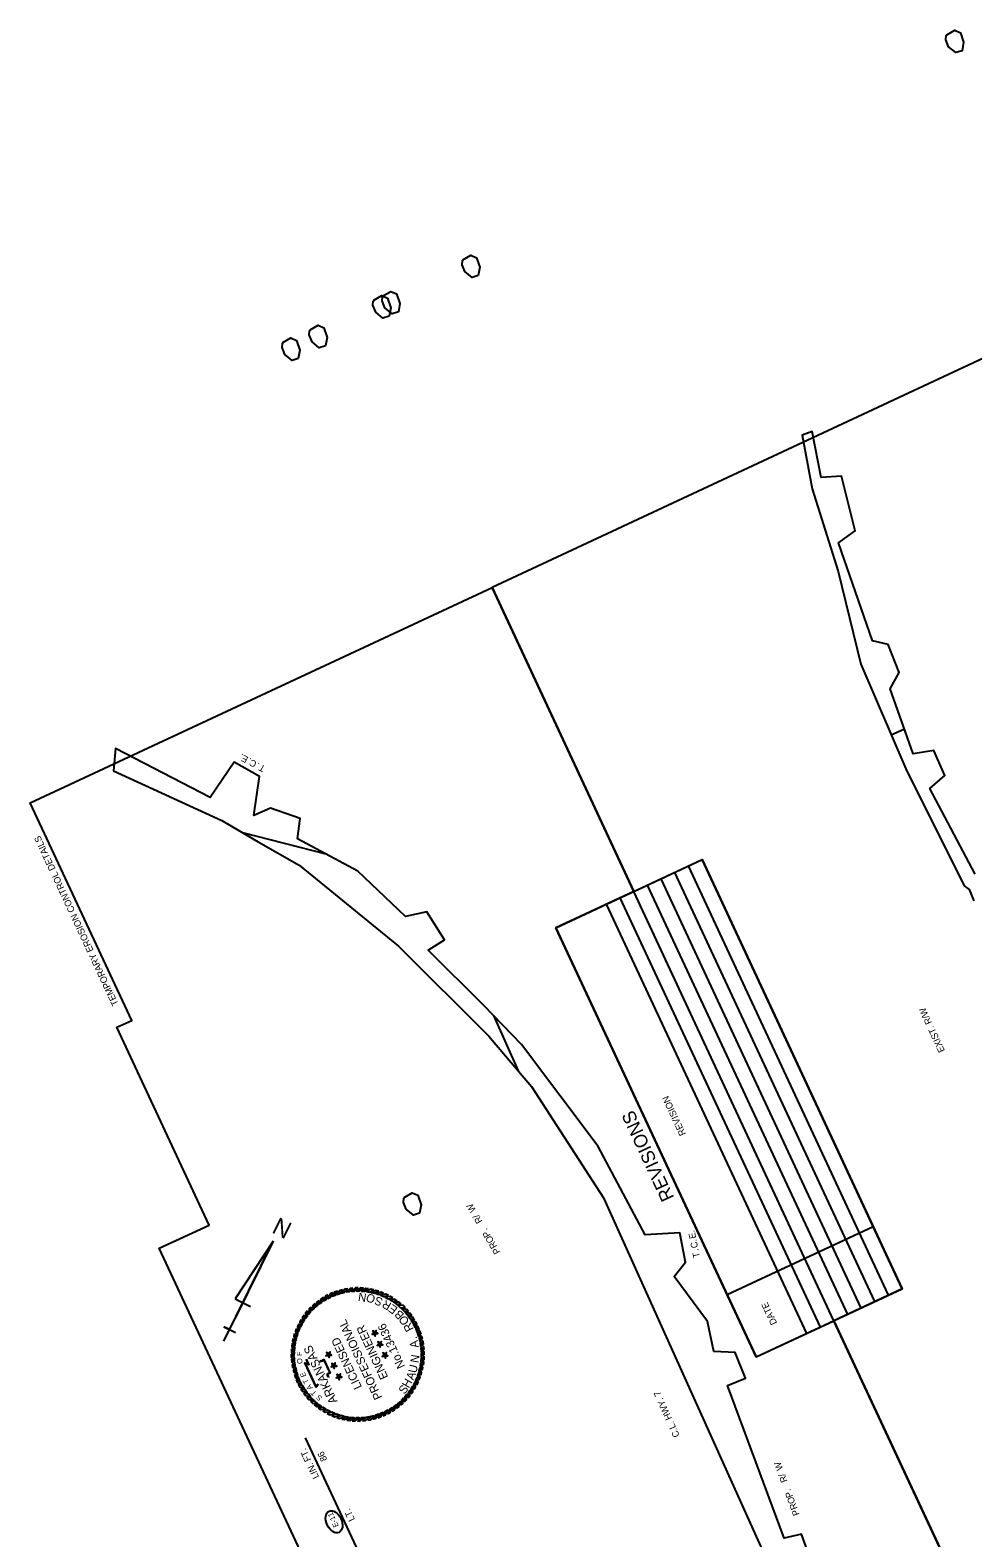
# Model space of a CAD drawing. Extents: x 964229 to 965790, y 1899262 to 1901428.
# Drawn here: x 964229 to 965075, y 1900076 to 1901428 of the extents above; entities that cross this region are included whole.
import ezdxf

# ---------------------------------------------------------------- set-up
doc = ezdxf.new("R2010")
doc.units = 0
for name, color, linetype in [('1', 7, 'Continuous'), ('44', 7, 'Continuous'), ('63', 7, 'Continuous'), ('Default', 7, 'Continuous'), ('G-ANNO-SYMB', 7, 'Continuous'), ('NO PLOT', 7, 'Continuous'), ('R_Draft', 7, 'Continuous'), ('R_Horz Alg Annot', 7, 'Continuous'), ('S_TREE', 7, 'Continuous')]:
    doc.layers.add(name, color=color, linetype=linetype)

msp = doc.modelspace()

# ---------------------------------------------------------------- linework, layer by layer
at = {"layer": '1'}
for p, q in [((964770.4, 1900655.6), (964643.2, 1900928.4)), ((965071, 1900011), (964950, 1900270.4))]:
    msp.add_line(p, q, dxfattribs=at)
msp.add_ellipse((964501.5, 1900090), major_axis=(-4.45, 9.53), ratio=0.638788, dxfattribs=at)
at = {"layer": '44'}
msp.add_line((964574.3, 1899954.5), (964475.9, 1900165.4), dxfattribs=at)
at = {"layer": '63'}
for p, q in [((964402.7, 1900252.1), (964447, 1900341.7)), ((964447, 1900341.7), (964412.8, 1900290)), ((964447, 1900341.7), (964412.9, 1900272.8)), ((964412.8, 1900290), (964426.6, 1900283.1)), ((964402.7, 1900252.1), (964412.9, 1900272.8)), ((964407.8, 1900262.4), (964402.6, 1900265)), ((964402.6, 1900265), (964413, 1900259.9)), ((964402.7, 1900252.1), (964407.8, 1900262.4))]:
    msp.add_line(p, q, dxfattribs=at)
at = {"layer": 'Default'}
for p, q in [((964700.6, 1900623), (964831.6, 1900684.1)), ((964999, 1900293.2), (964819.4, 1900678.4)), ((965011.2, 1900298.9), (964831.6, 1900684.1)), ((964974.5, 1900281.8), (964794.9, 1900667)), ((964986.7, 1900287.5), (964807.1, 1900672.7)), ((964937.8, 1900264.7), (964758.2, 1900649.9)), ((964950, 1900270.4), (964770.4, 1900655.6)), ((964962.3, 1900276.1), (964782.7, 1900661.3)), ((964962.3, 1900276.1), (964782.7, 1900661.3)), ((964925.6, 1900259), (964745.9, 1900644.2)), ((964880.2, 1900237.9), (964700.6, 1900623)), ((964854.1, 1900293.9), (964985.1, 1900354.9)), ((964880.2, 1900237.9), (965011.2, 1900298.9))]:
    msp.add_line(p, q, dxfattribs=at)
at = {"layer": 'G-ANNO-SYMB'}
for points in [[(964504.7, 1900297), (964502.3, 1900296.2), (964499.9, 1900292.3), (964502.4, 1900293.3)], [(964509.2, 1900298.2), (964506.7, 1900297.6), (964504, 1900293.9), (964506.7, 1900294.8)], [(964513.8, 1900299.1), (964511.3, 1900298.7), (964508.3, 1900295.2), (964511, 1900295.9)], [(964518.5, 1900299.7), (964515.9, 1900299.4), (964512.7, 1900296.2), (964515.4, 1900296.6)], [(964523.1, 1900299.8), (964520.6, 1900299.8), (964517.1, 1900296.8), (964519.9, 1900297)], [(964527.8, 1900299.6), (964525.3, 1900299.8), (964521.6, 1900297.1), (964524.3, 1900297.1)], [(964532.5, 1900299), (964529.9, 1900299.4), (964526, 1900297), (964528.8, 1900296.8)], [(964537.1, 1900298.1), (964534.6, 1900298.6), (964530.5, 1900296.6), (964533.2, 1900296.1)], [(964541.6, 1900296.8), (964539.1, 1900297.5), (964534.9, 1900295.8), (964537.6, 1900295.1)], [(964484.3, 1900285.8), (964482.4, 1900284.1), (964481.7, 1900279.5), (964483.6, 1900281.5)], [(964488, 1900288.6), (964486, 1900287.1), (964484.9, 1900282.7), (964487, 1900284.4)], [(964491.9, 1900291.2), (964489.7, 1900289.8), (964488.3, 1900285.5), (964490.6, 1900287.1)], [(964496, 1900293.5), (964493.7, 1900292.3), (964492, 1900288.1), (964494.4, 1900289.5)], [(964500.3, 1900295.4), (964497.9, 1900294.4), (964495.9, 1900290.3), (964498.3, 1900291.6)], [(964545.9, 1900295.1), (964543.6, 1900296.1), (964539.2, 1900294.7), (964541.8, 1900293.8)], [(964550.2, 1900293.1), (964547.9, 1900294.3), (964543.4, 1900293.2), (964546, 1900292.1)], [(964554.3, 1900290.8), (964552.1, 1900292.1), (964547.5, 1900291.4), (964550, 1900290.1)], [(964558.1, 1900288.2), (964556, 1900289.7), (964551.5, 1900289.3), (964553.8, 1900287.9)], [(964561.8, 1900285.3), (964559.8, 1900286.9), (964555.2, 1900286.9), (964557.5, 1900285.3)], [(964565.2, 1900282.1), (964563.4, 1900283.9), (964558.8, 1900284.2), (964560.9, 1900282.4)], [(964472.1, 1900271.6), (964470.8, 1900269.4), (964471.5, 1900264.9), (964472.8, 1900267.4)], [(964474.7, 1900275.5), (964473.2, 1900273.4), (964473.6, 1900268.9), (964475.1, 1900271.2)], [(964477.6, 1900279.2), (964476, 1900277.2), (964476, 1900272.6), (964477.6, 1900274.9)], [(964480.8, 1900282.6), (964479.1, 1900280.8), (964478.7, 1900276.2), (964480.5, 1900278.3)], [(964568.4, 1900278.6), (964566.7, 1900280.5), (964562.2, 1900281.2), (964564.1, 1900279.3)], [(964571.3, 1900274.9), (964569.7, 1900277), (964565.3, 1900278), (964567.1, 1900275.9)], [(964573.8, 1900271), (964572.5, 1900273.2), (964568.1, 1900274.6), (964569.7, 1900272.3)], [(964576.1, 1900266.9), (964574.9, 1900269.2), (964570.7, 1900270.9), (964572.1, 1900268.5)], [(964466.1, 1900258.9), (964465.4, 1900256.5), (964467.1, 1900252.3), (964467.8, 1900255)], [(964467.8, 1900263.3), (964466.8, 1900260.9), (964468.3, 1900256.6), (964469.1, 1900259.2)], [(964469.8, 1900267.6), (964468.7, 1900265.3), (964469.7, 1900260.8), (964470.8, 1900263.4)], [(964538, 1900259.3), (964537, 1900259.5), (964535.6, 1900258.2), (964537.5, 1900258.4)], [(964538, 1900259.3), (964537.9, 1900260.3), (964536.2, 1900261.3), (964537, 1900259.5)], [(964538, 1900259.3), (964537.5, 1900258.4), (964538.4, 1900256.6), (964538.7, 1900258.5)], [(964538, 1900259.3), (964539, 1900259.7), (964539.3, 1900261.7), (964537.9, 1900260.3)], [(964538, 1900259.3), (964538.7, 1900258.5), (964540.7, 1900258.8), (964539, 1900259.7)], [(964578, 1900262.6), (964577, 1900265), (964572.9, 1900267.1), (964574.2, 1900264.6)], [(964579.6, 1900258.2), (964578.8, 1900260.7), (964574.9, 1900263), (964575.9, 1900260.5)], [(964580.9, 1900253.7), (964580.2, 1900256.2), (964576.5, 1900258.9), (964577.4, 1900256.2)], [(964463.3, 1900245.2), (964463.2, 1900242.6), (964465.8, 1900238.9), (964465.9, 1900241.7)], [(964463.9, 1900249.9), (964463.5, 1900247.3), (964465.9, 1900243.4), (964466.2, 1900246.2)], [(964464.8, 1900254.4), (964464.3, 1900251.9), (964466.4, 1900247.9), (964466.8, 1900250.6)], [(964496.6, 1900240), (964497.6, 1900240.4), (964497.9, 1900242.4), (964496.5, 1900241)], [(964542.6, 1900249.4), (964541.6, 1900249.6), (964540.2, 1900248.3), (964542.1, 1900248.5)], [(964542.6, 1900249.4), (964542.5, 1900250.5), (964540.8, 1900251.4), (964541.6, 1900249.6)], [(964542.6, 1900249.4), (964542.1, 1900248.5), (964543, 1900246.7), (964543.3, 1900248.7)], [(964542.6, 1900249.4), (964543.6, 1900249.9), (964544, 1900251.8), (964542.5, 1900250.5)], [(964542.6, 1900249.4), (964543.3, 1900248.7), (964545.3, 1900248.9), (964543.6, 1900249.9)], [(964581.7, 1900249.1), (964581.3, 1900251.6), (964577.8, 1900254.6), (964578.5, 1900251.9)], [(964582.3, 1900244.5), (964582, 1900247), (964578.8, 1900250.2), (964579.2, 1900247.5)], [(964582.4, 1900239.8), (964582.4, 1900242.3), (964579.4, 1900245.8), (964579.6, 1900243.1)], [(964463.1, 1900240.5), (964463.1, 1900238), (964466.1, 1900234.5), (964465.9, 1900237.2)], [(964463.3, 1900235.8), (964463.5, 1900233.3), (964466.7, 1900230.1), (964466.3, 1900232.8)], [(964463.8, 1900231.2), (964464.2, 1900228.7), (964467.7, 1900225.7), (964467.1, 1900228.4)], [(964496.6, 1900240), (964495.6, 1900240.2), (964494.2, 1900238.8), (964496.1, 1900239.1)], [(964496.6, 1900240), (964496.5, 1900241), (964494.8, 1900242), (964495.6, 1900240.2)], [(964496.6, 1900240), (964496.1, 1900239.1), (964497, 1900237.3), (964497.3, 1900239.2)], [(964496.6, 1900240), (964497.3, 1900239.2), (964499.3, 1900239.5), (964497.6, 1900240.4)], [(964501.2, 1900230.1), (964500.2, 1900230.3), (964498.8, 1900229), (964500.7, 1900229.2)], [(964501.2, 1900230.1), (964501.1, 1900231.1), (964499.4, 1900232.1), (964500.2, 1900230.3)], [(964501.2, 1900230.1), (964500.7, 1900229.2), (964501.6, 1900227.4), (964501.9, 1900229.3)], [(964501.2, 1900230.1), (964502.2, 1900230.6), (964502.6, 1900232.5), (964501.1, 1900231.1)], [(964501.2, 1900230.1), (964501.9, 1900229.3), (964503.9, 1900229.6), (964502.2, 1900230.6)], [(964547.2, 1900239.5), (964546.2, 1900239.7), (964544.8, 1900238.4), (964546.7, 1900238.6)], [(964547.2, 1900239.5), (964547.1, 1900240.6), (964545.4, 1900241.5), (964546.2, 1900239.7)], [(964547.2, 1900239.5), (964546.7, 1900238.6), (964547.6, 1900236.8), (964548, 1900238.8)], [(964547.2, 1900239.5), (964548.2, 1900240), (964548.6, 1900241.9), (964547.1, 1900240.6)], [(964547.2, 1900239.5), (964548, 1900238.8), (964549.9, 1900239), (964548.2, 1900240)], [(964580.7, 1900225.9), (964581.2, 1900228.4), (964579.2, 1900232.4), (964578.7, 1900229.7)], [(964581.6, 1900230.4), (964582, 1900233), (964579.6, 1900236.9), (964579.4, 1900234.1)], [(964582.2, 1900235.1), (964582.4, 1900237.7), (964579.7, 1900241.4), (964579.7, 1900238.6)], [(964464.7, 1900226.6), (964465.3, 1900224.1), (964469, 1900221.4), (964468.2, 1900224.1)], [(964465.9, 1900222.1), (964466.7, 1900219.6), (964470.6, 1900217.3), (964469.6, 1900219.8)], [(964467.5, 1900217.7), (964468.5, 1900215.3), (964472.6, 1900213.2), (964471.3, 1900215.7)], [(964505.8, 1900220.2), (964504.8, 1900220.4), (964503.4, 1900219.1), (964505.3, 1900219.3)], [(964505.8, 1900220.2), (964505.7, 1900221.3), (964504, 1900222.2), (964504.8, 1900220.4)], [(964505.8, 1900220.2), (964505.3, 1900219.3), (964506.2, 1900217.5), (964506.6, 1900219.5)], [(964505.8, 1900220.2), (964506.8, 1900220.7), (964507.2, 1900222.6), (964505.7, 1900221.3)], [(964505.8, 1900220.2), (964506.6, 1900219.5), (964508.5, 1900219.7), (964506.8, 1900220.7)], [(964573.4, 1900208.7), (964574.7, 1900210.9), (964574, 1900215.4), (964572.8, 1900212.9)], [(964575.8, 1900212.7), (964576.9, 1900215), (964575.8, 1900219.5), (964574.7, 1900216.9)], [(964577.7, 1900217), (964578.7, 1900219.4), (964577.3, 1900223.7), (964576.4, 1900221.1)], [(964579.4, 1900221.4), (964580.1, 1900223.8), (964578.4, 1900228), (964577.7, 1900225.3)], [(964469.4, 1900213.4), (964470.6, 1900211.1), (964474.9, 1900209.4), (964473.4, 1900211.8)], [(964471.7, 1900209.3), (964473.1, 1900207.1), (964477.4, 1900205.7), (964475.8, 1900208)], [(964474.3, 1900205.4), (964475.8, 1900203.3), (964480.3, 1900202.3), (964478.5, 1900204.4)], [(964477.2, 1900201.7), (964478.9, 1900199.8), (964483.4, 1900199.1), (964481.4, 1900201)], [(964564.7, 1900197.7), (964566.5, 1900199.5), (964566.8, 1900204.1), (964565, 1900202)], [(964567.9, 1900201.1), (964569.5, 1900203.1), (964569.5, 1900207.7), (964567.9, 1900205.4)], [(964570.8, 1900204.8), (964572.3, 1900206.9), (964571.9, 1900211.4), (964570.5, 1900209.1)], [(964480.3, 1900198.2), (964482.2, 1900196.4), (964486.7, 1900196.1), (964484.6, 1900197.9)], [(964483.7, 1900195), (964485.7, 1900193.4), (964490.3, 1900193.4), (964488, 1900195)], [(964487.4, 1900192.1), (964489.5, 1900190.6), (964494.1, 1900191), (964491.7, 1900192.4)], [(964491.3, 1900189.5), (964493.5, 1900188.2), (964498, 1900188.9), (964495.5, 1900190.2)], [(964495.3, 1900187.2), (964497.6, 1900186), (964502.1, 1900187.1), (964499.5, 1900188.2)], [(964540.8, 1900183.3), (964543.3, 1900184.1), (964545.7, 1900188), (964543.1, 1900187)], [(964545.2, 1900184.9), (964547.6, 1900185.9), (964549.7, 1900190), (964547.2, 1900188.7)], [(964549.5, 1900186.8), (964551.8, 1900188), (964553.5, 1900192.2), (964551.2, 1900190.8)], [(964553.6, 1900189.1), (964555.8, 1900190.5), (964557.2, 1900194.8), (964554.9, 1900193.2)], [(964557.5, 1900191.7), (964559.6, 1900193.2), (964560.6, 1900197.7), (964558.5, 1900195.9)], [(964561.2, 1900194.5), (964563.1, 1900196.2), (964563.9, 1900200.8), (964561.9, 1900198.8)], [(964499.6, 1900185.2), (964502, 1900184.2), (964506.3, 1900185.6), (964503.7, 1900186.5)], [(964504, 1900183.5), (964506.4, 1900182.8), (964510.6, 1900184.5), (964508, 1900185.2)], [(964508.5, 1900182.2), (964511, 1900181.7), (964515, 1900183.7), (964512.3, 1900184.2)], [(964513.1, 1900181.3), (964515.6, 1900180.9), (964519.5, 1900183.3), (964516.7, 1900183.5)], [(964517.7, 1900180.7), (964520.3, 1900180.5), (964524, 1900183.2), (964521.2, 1900183.2)], [(964522.4, 1900180.5), (964525, 1900180.5), (964528.4, 1900183.5), (964525.7, 1900183.3)], [(964527.1, 1900180.6), (964529.6, 1900180.9), (964532.9, 1900184.1), (964530.1, 1900183.7)], [(964531.7, 1900181.2), (964534.3, 1900181.6), (964537.2, 1900185.1), (964534.5, 1900184.4)], [(964536.3, 1900182.1), (964538.8, 1900182.7), (964541.5, 1900186.4), (964538.9, 1900185.5)]]:
    msp.add_lwpolyline(points, close=True, dxfattribs=at)
for points in [[(964487.6, 1900213.2), (964485.4, 1900210.7), (964475.2, 1900232.5), (964478.4, 1900231.7), (964477.7, 1900233.2), (964477.1, 1900234.4), (964476.6, 1900235.7)], [(964487.3, 1900213.4), (964485.5, 1900211.4), (964475.9, 1900231.9), (964479.1, 1900231.1), (964478, 1900233.3), (964477.4, 1900234.6), (964477, 1900235.8)], [(964488.6, 1900234.2), (964489.1, 1900233.9), (964489.8, 1900234), (964491, 1900234.5), (964492.2, 1900235), (964497.6, 1900223.5), (964495.9, 1900222.7), (964495.2, 1900222.4), (964495.3, 1900221.5), (964496, 1900219.9), (964495.8, 1900219.6)], [(964488.7, 1900234.6), (964489.2, 1900234.3), (964489.7, 1900234.4), (964490.9, 1900234.8), (964492.4, 1900235.5), (964498.1, 1900223.4), (964496, 1900222.4), (964495.6, 1900222.2), (964495.7, 1900221.6), (964496.5, 1900219.9), (964496.2, 1900219.4)]]:
    msp.add_lwpolyline(points, dxfattribs=at)
at = {"layer": 'NO PLOT'}
for points in [[(965789.8, 1899702.7), (965115.5, 1901148.6), (964643.2, 1900928.4), (964770.4, 1900655.6), (964831.6, 1900684.1), (965011.2, 1900298.9), (964950, 1900270.4), (965071, 1900011), (965127, 1900037.1), (965271.8, 1899726.6), (965215.8, 1899700.5), (965317.4, 1899482.5)], [(965789.8, 1899702.7), (965115.5, 1901148.6), (964643.2, 1900928.4), (964770.4, 1900655.6), (964831.6, 1900684.1), (965011.2, 1900298.9), (964950, 1900270.4), (965071, 1900011), (965127, 1900037.1), (965271.8, 1899726.6), (965215.8, 1899700.5), (965317.4, 1899482.5)], [(965789.8, 1899702.7), (965115.5, 1901148.6), (964643.2, 1900928.4), (964770.4, 1900655.6), (964831.6, 1900684.1), (965011.2, 1900298.9), (964950, 1900270.4), (965071, 1900011), (965127, 1900037.1), (965271.8, 1899726.6), (965215.8, 1899700.5), (965317.4, 1899482.5)], [(964845.1, 1899262.2), (964344.7, 1900335.4), (964389.5, 1900356.2), (964306.7, 1900533.7), (964320, 1900539.9), (964228.9, 1900735.2), (964643.2, 1900928.4), (964770.4, 1900655.6), (964700.6, 1900623), (964880.2, 1900237.9), (964950, 1900270.4), (965071, 1900011), (965017.2, 1899986), (965162.1, 1899675.4), (965215.8, 1899700.5), (965317.4, 1899482.5)], [(964845.1, 1899262.2), (964344.7, 1900335.4), (964389.5, 1900356.2), (964306.7, 1900533.7), (964320, 1900539.9), (964228.9, 1900735.2), (964643.2, 1900928.4), (964770.4, 1900655.6), (964700.6, 1900623), (964880.2, 1900237.9), (964950, 1900270.4), (965071, 1900011), (965017.2, 1899986), (965162.1, 1899675.4), (965215.8, 1899700.5), (965317.4, 1899482.5)], [(964845.1, 1899262.2), (964344.7, 1900335.4), (964389.5, 1900356.2), (964306.7, 1900533.7), (964320, 1900539.9), (964228.9, 1900735.2), (964643.2, 1900928.4), (964770.4, 1900655.6), (964700.6, 1900623), (964880.2, 1900237.9), (964950, 1900270.4), (965071, 1900011), (965017.2, 1899986), (965162.1, 1899675.4), (965215.8, 1899700.5), (965317.4, 1899482.5)]]:
    msp.add_lwpolyline(points, close=True, dxfattribs=at)
for points in [[(965076.5, 1900671.2), (965035.9, 1900747.8), (965049.4, 1900759.7), (965039.7, 1900781.9), (965020.9, 1900779.1), (965000.4, 1900837.5), (965008.5, 1900851.9), (964998.5, 1900877.1), (964984.6, 1900880.5), (964954.1, 1900968.5), (964968.9, 1900979.2), (964956.6, 1901028.1), (964938.5, 1901027), (964930.5, 1901068.3), (964921.5, 1901064.9), (964930.5, 1901016.9), (964953.6, 1900942.5), (964974, 1900859.4), (965014.3, 1900765.5), (965066.7, 1900660.7), (965071.2, 1900657.4), (965075.4, 1900647.1)], [(964930.5, 1900052.3), (964920.8, 1900078.8), (964905.4, 1900075.2), (964854.4, 1900212.3), (964870.5, 1900218.8), (964861.3, 1900241.9), (964842.2, 1900242.8), (964836.4, 1900269.6), (964806.7, 1900310.1), (964816.7, 1900323), (964811.8, 1900349.2), (964780.5, 1900347.5), (964738.4, 1900426.6), (964669.8, 1900518.3), (964635.9, 1900553.2), (964585.9, 1900602.8), (964600.6, 1900612.2), (964584.7, 1900637.4), (964565.5, 1900633.1), (964522.8, 1900673.7), (964468.8, 1900702.8), (964471.2, 1900721), (964444.6, 1900730.3), (964429.6, 1900723.8), (964434.5, 1900758.7), (964412, 1900771.5), (964390.5, 1900739.8), (964305.3, 1900783.8), (964303.7, 1900763.9), (964400.7, 1900719.2), (964433.3, 1900700.2), (964470.1, 1900679.1), (964559.3, 1900606.4), (964640.4, 1900525.8), (964678.6, 1900480.5), (964743.2, 1900380.8), (964921.4, 1899985.4)]]:
    msp.add_lwpolyline(points, dxfattribs=at)
at = {"layer": 'R_Horz Alg Annot'}
for p, q in [((964494.3, 1900689.1), (964419.6, 1900708.2)), ((964644.4, 1900544.4), (964666.7, 1900494.7))]:
    msp.add_line(p, q, dxfattribs=at)
msp.add_lwpolyline([(965001.2, 1900796.1), (965013.1, 1900801.4)], dxfattribs=at)
at = {"layer": 'S_TREE'}
for points in [[(965051.2, 1901424.3), (965058.3, 1901428.4), (965063.4, 1901426.1), (965066.3, 1901417.5), (965065, 1901409.9), (965059.4, 1901408.2), (965052.8, 1901413.5), (965050.4, 1901419.8), (965050.7, 1901423.5), (965051.8, 1901424.8)], [(964617.1, 1901222.4), (964624.2, 1901226.5), (964629.3, 1901224.2), (964632.2, 1901215.6), (964630.9, 1901208.1), (964625.3, 1901206.3), (964618.8, 1901211.7), (964616.3, 1901217.9), (964616.6, 1901221.6), (964617.7, 1901222.9)], [(964537.2, 1901186.1), (964544.3, 1901190.2), (964549.4, 1901187.9), (964552.3, 1901179.3), (964551, 1901171.8), (964545.4, 1901170), (964538.9, 1901175.3), (964536.4, 1901181.6), (964536.7, 1901185.3), (964537.8, 1901186.6)], [(964537.2, 1901186.1), (964544.3, 1901190.2), (964549.4, 1901187.9), (964552.3, 1901179.3), (964551, 1901171.8), (964545.4, 1901170), (964538.9, 1901175.3), (964536.4, 1901181.6), (964536.7, 1901185.3), (964537.8, 1901186.6)], [(964545.3, 1901189.9), (964552.5, 1901194), (964557.5, 1901191.7), (964560.4, 1901183.1), (964559.2, 1901175.6), (964553.6, 1901173.8), (964547, 1901179.2), (964544.6, 1901185.4), (964544.9, 1901189.1), (964546, 1901190.4)], [(964480.1, 1901159.5), (964487.2, 1901163.6), (964492.3, 1901161.3), (964495.2, 1901152.7), (964493.9, 1901145.2), (964488.3, 1901143.4), (964481.8, 1901148.7), (964479.3, 1901155), (964479.6, 1901158.7), (964480.7, 1901160)], [(964455.6, 1901148.1), (964462.8, 1901152.2), (964467.8, 1901149.9), (964470.7, 1901141.3), (964469.4, 1901133.7), (964463.9, 1901132), (964457.3, 1901137.3), (964454.9, 1901143.6), (964455.2, 1901147.3), (964456.2, 1901148.6)], [(964564.5, 1900381.1), (964571.6, 1900385.2), (964576.7, 1900382.9), (964579.6, 1900374.3), (964578.3, 1900366.8), (964572.8, 1900365), (964566.2, 1900370.4), (964563.8, 1900376.6), (964564.1, 1900380.3), (964565.1, 1900381.6)]]:
    msp.add_lwpolyline(points, dxfattribs=at)

# ---------------------------------------------------------------- texts
at = {"layer": '1'}
for s, height, p in [('TEMPORARY EROSION CONTROL DETAILS', 6, (964308.3, 1900554.6)), ('E-11', 4.8, (964505.8, 1900086.3))]:
    msp.add_text(s, height=height, rotation=115, dxfattribs=at).set_placement(p)
at = {"layer": '44'}
for s, p in [('LIN. FT.', (964488.2, 1900130.2)), ('86', (964495.5, 1900145.7)), ('LT.', (964520.4, 1900092))]:
    msp.add_text(s, height=6, rotation=115, dxfattribs=at).set_placement(p)
at = {"layer": '63'}
msp.add_text('N', height=15.4, rotation=333.6555, dxfattribs=at).set_placement((964444.8, 1900349.9))
at = {"layer": 'Default'}
for s, height, p in [('REVISION', 6, (964817.3, 1900438)), ('REVISIONS', 12, (964806.9, 1900380.9)), ('DATE', 6, (964899.1, 1900268.3))]:
    msp.add_text(s, height=height, rotation=115, dxfattribs=at).set_placement(p)
at = {"layer": 'G-ANNO-SYMB'}
for s, height, rotation, p in [('N', 7.5, 171.1007, (964531, 1900294.5)), ('O', 7.5, 159.7757, (964539.3, 1900292.6)), ('S', 7.5, 158.4878, (964546, 1900290)), ('R', 7.5, 150.6597, (964553.6, 1900285.9)), ('E', 7.5, 142.8315, (964559.2, 1900281.6)), ('PROFESSIONAL', 7.5, 115, (964544.9, 1900201.6)), ('B', 7.5, 133.885, (964564.9, 1900275.9)), ('O', 7.5, 126.4296, (964569.5, 1900269.7)), ('ENGINEER', 7.5, 115, (964550.2, 1900219.8)), ('No.13436', 7.47, 115, (964565.4, 1900229.5)), ('R', 7.5, 118.2287, (964573.2, 1900263)), ('.', 7.5, 106.3, (964576.2, 1900254.2)), ('F', 4.75, 90.3628, (964472.9, 1900238.8)), ('ARKANSAS', 7.75, 115, (964504.8, 1900198)), ('LICENSED', 7.5, 115, (964526.7, 1900210.9)), ('A', 7.5, 98.0991, (964577.4, 1900246.6)), ('O', 4.75, 96.2218, (964473.3, 1900231.9)), ('U', 7.5, 75.9026, (964575.2, 1900222.9)), ('N', 7.5, 79.9326, (964577.1, 1900232.1)), ('E', 4.75, 111.672, (964476.7, 1900220.8)), ('T', 4.75, 116.4789, (964479.2, 1900215.2)), ('H', 7.5, 60.619, (964568.5, 1900209.4)), ('A', 7.5, 68.4472, (964572.7, 1900216.6)), ('A', 4.75, 123.6788, (964482.6, 1900210.1)), ('T', 4.75, 131.9015, (964486.4, 1900205.5)), ('S', 4.75, 134.7726, (964491.4, 1900201.2)), ('S', 7.5, 53.1636, (964564.7, 1900203.8))]:
    msp.add_text(s, height=height, rotation=rotation, dxfattribs=at).set_placement(p)
at = {"layer": 'R_Draft'}
for s, rotation, p in [('E', 151.6628, (964425.1, 1900775.8)), ('.', 151.6628, (964420.4, 1900778.4)), ('C', 151.6628, (964432.7, 1900771.7)), ('.', 151.6628, (964427.7, 1900774.4)), ('.', 151.6628, (964435.2, 1900770.3)), ('T', 151.6628, (964440.4, 1900767.6)), ('EXIST. R/W', 114.616, (965049.6, 1900512.7)), ('W', 120.1833, (964629.1, 1900369.7)), ('/', 120.1833, (964632, 1900364.6)), ('R', 120.1833, (964634.9, 1900359.7)), ('.', 120.1833, (964639.4, 1900352)), ('.', 101.3937, (964825.3, 1900349.8)), ('P', 120.1833, (964642.2, 1900347.1)), ('O', 120.1833, (964645.2, 1900342)), ('R', 120.1833, (964648, 1900337.1)), ('E', 101.3937, (964826.4, 1900344.6)), ('C', 101.3937, (964828.1, 1900336.1)), ('.', 101.3937, (964827, 1900341.7)), ('P', 120.1833, (964650.9, 1900332.2)), ('T', 101.3937, (964829.8, 1900327.5)), ('.', 101.3937, (964828.7, 1900333.3)), ('C.L. HWY. 7', 114.0156, (964811.7, 1900167.3)), ('W', 110.1463, (964904.4, 1900137.3)), ('/', 110.1463, (964906.4, 1900131.8)), ('R', 110.1463, (964908.4, 1900126.5)), ('P', 110.1463, (964913.4, 1900112.8)), ('O', 110.1463, (964915.4, 1900107.3)), ('.', 110.1463, (964911.5, 1900118.1)), ('R', 110.1463, (964917.4, 1900102)), ('P', 110.1463, (964919.3, 1900096.7))]:
    msp.add_text(s, height=6, rotation=rotation, dxfattribs=at).set_placement(p)

doc.saveas('drawing.dxf')
